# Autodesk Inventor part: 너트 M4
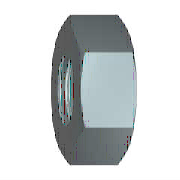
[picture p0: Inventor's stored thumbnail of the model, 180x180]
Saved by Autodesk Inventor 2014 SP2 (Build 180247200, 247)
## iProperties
Created: 2012-02
Part Number: 너트 M4
Material: 강철, 연강
Description: 6각 너트 및 6각 가는 너트 - 스타일 1
Document SubType Name: Modeling
Standard: KS B 1012
Designer: mduedu
Standards Organization: KS
Language: ko-KR
Size Designation: A M4
Categories: <MemberInstance><Categories><Category DisplayName="조임쇠" InternalName="e4da775c-781d-43d5-af7c-5136215cf5a6" Mnemonic="FSTN"><Category DisplayName="너트" InternalN
Density: 7.86 g/cm^3
Appearance: 강철
Mass: 0.846697 g
Surface Area: 1.71448 cm^2
Volume: 0.107722 cm^3
IsCustomPart: 0
Author: mduedu
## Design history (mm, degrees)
sketch "스케치1"
  geometry: L1 (-4.041, 0)-(-2.021, 3.5); L2 (-2.021, 3.5)-(2.021, 3.5); L3 (2.021, 3.5)-(4.041, 0); L4 (4.041, 0)-(2.021, -3.5); L5 (2.021, -3.5)-(-2.021, -3.5); L6 (-2.021, -3.5)-(-4.041, 0); 2 further points
  constraints: 12 end point, 1 coincident, 1 horizontal, 11 other
  dimensions: "d0" = 8.0829 distance of L3.end L1.start (= 1.1547 x SW)
extrude "본체" new body sketch "스케치1" distance "d1" = 3.2 (= KOH); taper "d2" = 0 deg
sketch "스케치2"
  geometry: L1 (0, 2.021)-(0, 4.041) reference; L2 (0, 4.041)-(3.2, 4.041) reference; L3 (3.2, 2.021)-(3.2, 4.041) reference; L4 (-0.64, 0)-(3.84, 0) reference; L5 (0.313, 4.041)-(0, 3.5); L6 (2.887, 4.041)-(3.2, 3.5)
  constraints: 4 end point, 4 point on line
  dimensions: "d3" = 30 deg angle of L1 L5 (= ANG1); "d4" = 30 deg angle of L3 L6 (= ANG2); "d5" = 7 diameter of L5.end L4 (= SW0); "d6" = 7 diameter of L6.end L4 (= SW01)
revolve "모따기1" sketch "스케치2" stored, may be unused: angle "d7" = 90 deg
sketch "스케치3"
  geometry: A1 r 3.5 centre (0, 0) between (-1.75, -3.031) and (1.75, -3.031) reference; 1 further point
  constraints: 1 coincident
hole "스레드" sketch "스케치3" at (0, 0) diameter "d25" = 3.242; stored, may be unused: countersink angle "d29" = 82 deg, drill point angle "d31" = 118 deg; dims "d26" = 6, "d27" = 4, "d28" = 2, "d30" = 8
workaxis "Work Axis1"
workplane "Work Plane1"
body "Solid1"
chamfer "모따기2" distance "d8" = 0.37889 (= -0.5 x GD1 + 0.5 x NND); stored, may be unused: angle "d9" = 30 deg, second distance "d40" = 0.37889 (= -0.5 x GD1 + 0.5 x NND)
chamfer "모따기3" distance "d10" = 0.37889 (= -0.5 x GD1 + 0.5 x NND); stored, may be unused: angle "d11" = 30 deg, second distance "d41" = 0.37889 (= -0.5 x GD1 + 0.5 x NND)
other parameters: "ANG1" = 30 deg [user parameter; used in 1 equation term], "ANG2" = 30 deg [user parameter; used in 1 equation term], "NND" = 4 [user parameter; used in 4 equation terms], "KOH" = 3.2 [user parameter; used in 1 equation term], "SW" = 7 [user parameter; used in 4 equation terms], "SW0" = 7 (= SW) [user parameter; used in 1 equation term], "SW01" = 7 (= SW) [user parameter; used in 1 equation term], "GD1" = 3.24223 (computed from THREADDIA, PTC, TOA) [user parameter; used in 4 equation terms], "d13" = 0, "d14" = 0, "d39" = 0, "d42" = 0, "GUL" = 0.37889 (= 0.541266 x PTC) [user parameter], "TPU" = 14.28571 (computed from PTC) [user parameter], "THREADDIA" = 4 [user parameter; used in 1 equation term], "TOA" = 30 deg [user parameter; used in 1 equation term], "PTC" = 0.7 [user parameter; used in 4 equation terms], "E0" = 8.085 (= 1.155 x SW) [user parameter], "GAL" = 0.37889 (= 0.541266 x PTC) [user parameter]
